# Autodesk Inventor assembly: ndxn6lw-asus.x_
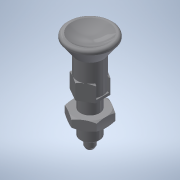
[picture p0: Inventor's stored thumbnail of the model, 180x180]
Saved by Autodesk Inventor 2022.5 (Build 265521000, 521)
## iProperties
Part Number: ndxn6lw-asus.x_
Material: 一般
Document SubType Name: Assembly
Designer: ImaoCorp
Sending System: SOLIDWORKS 2017-2017317
MC: AMD64
MC_MODEL: Intel64 Family 6 Model 60 Stepping 3, GenuineIntel
OS: Windows_NT
FRU: Parasolid Version 29.0, build 201,  4-17-2017
FORMAT: text
GUISE: transmit
KEY: ndxn6lw-asus
FILE: ndxn6lw-asus.x_t
DATE: Wed Sep 04 15:27:42 2019
Author: ImaoCorp
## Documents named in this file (3)
- X:\14_SW2022-Inv2022\00_全2023-1023新製品(TCC)まで\n\ndxn6lw-asus\NDXN6LW-ASUS.iam
- X:\14_SW2022-Inv2022\00_全2023-1023新製品(TCC)まで\n\ndxn6lw-asus\ndxn6lw-asus_01.ipt
- X:\14_SW2022-Inv2022\00_全2023-1023新製品(TCC)まで\n\ndxn6lw-asus\ndxn6lw-asus_02.ipt
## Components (2 placed, 2 different names)
1. ndxn6lw-asus_01
2. ndxn6lw-asus_02
